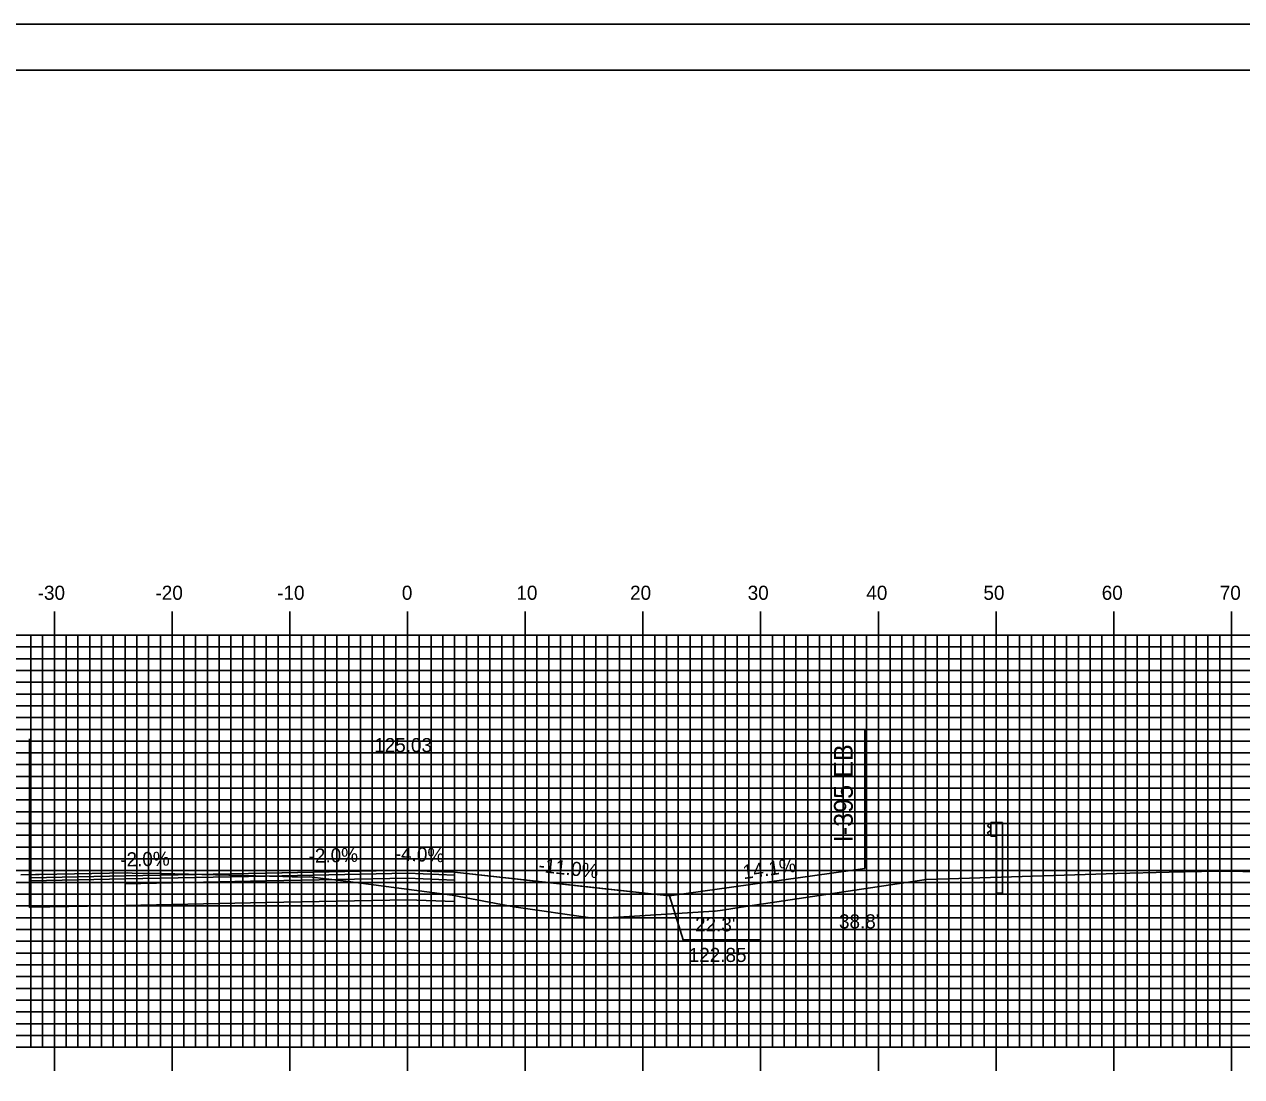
# Model space of a CAD drawing. Extents: x 853107 to 853450, y 366605 to 366825.
# Drawn here: x 853239.9 to 853343.4, y 366735.6 to 366824.9 of the extents above; entities that cross this region are included whole.
import ezdxf

# ---------------------------------------------------------------- set-up
doc = ezdxf.new("R2010")
doc.units = 0
for name, color, linetype in [('ANNOTATION', 7, 'Continuous'), ('BORDER', 7, 'Continuous'), ('D_Drainage_Underdrain', 7, 'Continuous'), ('D_Roadway_Centerline', 7, 'Continuous'), ('D_Roadway_Centerline_Text', 7, 'Continuous'), ('D_Roadway_Edge_Shoulder', 7, 'Continuous'), ('D_Roadway_Edge_TW', 7, 'Continuous'), ('D_Roadway_Pavement', 7, 'Continuous'), ('D_Roadway_SubGrade', 7, 'Continuous'), ('D_Text_Standard', 7, 'Continuous'), ('H_V ANNOTATION', 7, 'Continuous'), ('M_Guardrail', 7, 'Continuous'), ('M_Roadway_Centerline', 7, 'Continuous'), ('MAJOR', 7, 'Continuous'), ('MINOR', 7, 'Continuous'), ('PLOT BOUNDARY', 7, 'Continuous'), ('S_Roadway_Centerline', 7, 'Continuous')]:
    doc.layers.add(name, color=color, linetype=linetype)

msp = doc.modelspace()

# ---------------------------------------------------------------- linework, layer by layer
at = {"layer": 'ANNOTATION'}
msp.add_lwpolyline([(853302.45, 366747.17), (853295.91, 366747.17), (853294.76, 366750.91)], dxfattribs=at)
at = {"layer": 'BORDER'}
msp.add_lwpolyline([(853122.9, 366611.06), (853442.9, 366611.06), (853442.9, 366821.06), (853122.9, 366821.06)], close=True, dxfattribs=at)
at = {"layer": 'D_Drainage_Underdrain'}
msp.add_line((853240.42, 366752.43), (853240.39, 366752.44), dxfattribs=at)
at = {"layer": 'D_Roadway_Centerline'}
for p, q in [((853240.42, 366752.43), (853240.39, 366752.44)), ((853240.5, 366749.95), (853240.39, 366749.94))]:
    msp.add_line(p, q, dxfattribs=at)
for points in [[(853240.42, 366752.43), (853240.5, 366752.44), (853240.5, 366752.44), (853240.51, 366752.44), (853248.5, 366752.61), (853260.5, 366752.85), (853260.51, 366752.85), (853272.5, 366753.09), (853274.72, 366753), (853276.5, 366752.93), (853287.71, 366751.69), (853294.76, 366750.91)], [(853276.5, 366752.93), (853294.76, 366750.91)], [(853294.76, 366750.91), (853311.35, 366753.24)]]:
    msp.add_lwpolyline(points, dxfattribs=at)
at = {"layer": 'D_Roadway_Edge_Shoulder'}
for points in [[(853272.5, 366753.09), (853276.5, 366752.93), (853276.5, 366752.68), (853272.5, 366752.84)], [(853248.5, 366752.61), (853240.5, 366752.44), (853240.5, 366752.19), (853248.5, 366752.36)]]:
    msp.add_lwpolyline(points, close=True, dxfattribs=at)
at = {"layer": 'D_Roadway_Edge_TW'}
for points in [[(853260.5, 366752.85), (853248.5, 366752.61), (853248.5, 366752.36), (853260.5, 366752.6)], [(853272.5, 366753.09), (853260.5, 366752.85), (853260.5, 366752.6), (853272.5, 366752.84)]]:
    msp.add_lwpolyline(points, close=True, dxfattribs=at)
at = {"layer": 'D_Roadway_Pavement'}
for points in [[(853272.5, 366752.84), (853260.5, 366752.6), (853260.5, 366752.18), (853272.5, 366752.42)], [(853272.5, 366752.84), (853276.5, 366752.68), (853276.5, 366752.26), (853272.5, 366752.42)], [(853260.5, 366752.6), (853248.5, 366752.36), (853248.5, 366751.94), (853260.5, 366752.18)], [(853248.5, 366752.36), (853248.5, 366751.94), (853248.5, 366751.94)]]:
    msp.add_lwpolyline(points, close=True, dxfattribs=at)
msp.add_lwpolyline([(853260.5, 366752.6), (853260.5, 366752.18)], dxfattribs=at)
at = {"layer": 'D_Roadway_SubGrade'}
for p, q in [((853240.39, 366764.25), (853240.39, 366749.94)), ((853311.35, 366765.05), (853311.35, 366753.24)), ((853240.39, 366752.44), (853240.39, 366749.94))]:
    msp.add_line(p, q, dxfattribs=at)
for points in [[(853272.5, 366752.42), (853276.5, 366752.26), (853276.5, 366752.68), (853276.5, 366752.93), (853276.5, 366750.43), (853272.5, 366750.59)], [(853248.5, 366751.94), (853248.5, 366751.94), (853248.5, 366752.36), (853240.5, 366752.19), (853240.5, 366752.44), (853240.5, 366749.95), (853248.5, 366750.11)], [(853260.5, 366752.18), (853248.5, 366751.94), (853248.5, 366750.11), (853260.5, 366750.35)], [(853272.5, 366752.42), (853260.5, 366752.18), (853260.5, 366750.35), (853272.5, 366750.59)]]:
    msp.add_lwpolyline(points, close=True, dxfattribs=at)
at = {"layer": 'M_Guardrail'}
for p, q in [((853321.97, 366757.05), (853321.82, 366756.95)), ((853322.06, 366757.07), (853321.98, 366757.06)), ((853322.06, 366757.15), (853322.55, 366757.15)), ((853322.06, 366755.98), (853322.06, 366757.15)), ((853322.55, 366757.15), (853323.05, 366757.15)), ((853322.55, 366757.15), (853322.55, 366755.98)), ((853323.05, 366757.15), (853323.05, 366751.15)), ((853321.82, 366756.81), (853322.02, 366756.67)), ((853322.02, 366756.45), (853321.82, 366756.32)), ((853321.82, 366756.17), (853321.97, 366756.07)), ((853321.98, 366756.07), (853322.06, 366756.05)), ((853322.05, 366756.61), (853322.05, 366756.52)), ((853322.55, 366755.98), (853322.06, 366755.98)), ((853322.55, 366751.15), (853322.55, 366755.98)), ((853322.55, 366751.15), (853323.05, 366751.15))]:
    msp.add_line(p, q, dxfattribs=at)
for centre, major_axis, start_param, end_param in [((853321.87, 366756.88), (-0.0877, 0), 5.323254, 7.243116), ((853321.99, 366757.02), (-0.0417, 0), 4.886922, 5.323254), ((853321.87, 366756.25), (-0.0877, 0), 5.323254, 7.243116), ((853321.99, 366756.11), (-0.0417, 0), 0.959931, 1.396263), ((853321.97, 366756.61), (0.0789, 0), 0, 0.959931), ((853321.97, 366756.52), (0.0789, 0), 5.323254, 6.283185)]:
    msp.add_ellipse(centre, major_axis=major_axis, ratio=0.995501, start_param=start_param, end_param=end_param, dxfattribs=at)
at = {"layer": 'MAJOR'}
for p, q in [((853242.5, 366775.06), (853242.5, 366773.06)), ((853252.5, 366775.06), (853252.5, 366773.06)), ((853262.5, 366775.06), (853262.5, 366773.06)), ((853272.5, 366775.06), (853272.5, 366773.06)), ((853282.5, 366775.06), (853282.5, 366773.06)), ((853292.5, 366775.06), (853292.5, 366773.06)), ((853302.5, 366775.06), (853302.5, 366773.06)), ((853312.5, 366775.06), (853312.5, 366773.06)), ((853322.5, 366775.06), (853322.5, 366773.06)), ((853332.5, 366775.06), (853332.5, 366773.06)), ((853342.5, 366775.06), (853342.5, 366773.06)), ((853132.5, 366773.06), (853412.5, 366773.06)), ((853132.5, 366773.06), (853412.5, 366773.06)), ((853242.5, 366738.06), (853242.5, 366773.06)), ((853252.5, 366738.06), (853252.5, 366773.06)), ((853262.5, 366738.06), (853262.5, 366773.06)), ((853272.5, 366738.06), (853272.5, 366773.06)), ((853282.5, 366738.06), (853282.5, 366773.06)), ((853292.5, 366738.06), (853292.5, 366773.06)), ((853302.5, 366738.06), (853302.5, 366773.06)), ((853312.5, 366738.06), (853312.5, 366773.06)), ((853322.5, 366738.06), (853322.5, 366773.06)), ((853332.5, 366738.06), (853332.5, 366773.06)), ((853342.5, 366738.06), (853342.5, 366773.06)), ((853132.5, 366768.06), (853412.5, 366768.06)), ((853132.5, 366763.06), (853412.5, 366763.06)), ((853132.5, 366758.06), (853412.5, 366758.06)), ((853132.5, 366753.06), (853412.5, 366753.06)), ((853132.5, 366748.06), (853412.5, 366748.06)), ((853132.5, 366743.06), (853412.5, 366743.06)), ((853132.5, 366738.06), (853412.5, 366738.06)), ((853132.5, 366738.06), (853412.5, 366738.06)), ((853242.5, 366736.05), (853242.5, 366738.06)), ((853252.5, 366736.05), (853252.5, 366738.06)), ((853262.5, 366736.05), (853262.5, 366738.06)), ((853272.5, 366736.05), (853272.5, 366738.06)), ((853282.5, 366736.05), (853282.5, 366738.06)), ((853292.5, 366736.05), (853292.5, 366738.06)), ((853302.5, 366736.05), (853302.5, 366738.06)), ((853312.5, 366736.05), (853312.5, 366738.06)), ((853322.5, 366736.05), (853322.5, 366738.06)), ((853332.5, 366736.05), (853332.5, 366738.06)), ((853342.5, 366736.05), (853342.5, 366738.06))]:
    msp.add_line(p, q, dxfattribs=at)
at = {"layer": 'MINOR'}
for p, q in [((853240.5, 366738.06), (853240.5, 366773.06)), ((853241.5, 366738.06), (853241.5, 366773.06)), ((853243.5, 366738.06), (853243.5, 366773.06)), ((853244.5, 366738.06), (853244.5, 366773.06)), ((853245.5, 366738.06), (853245.5, 366773.06)), ((853246.5, 366738.06), (853246.5, 366773.06)), ((853247.5, 366738.06), (853247.5, 366773.06)), ((853248.5, 366738.06), (853248.5, 366773.06)), ((853249.5, 366738.06), (853249.5, 366773.06)), ((853250.5, 366738.06), (853250.5, 366773.06)), ((853251.5, 366738.06), (853251.5, 366773.06)), ((853253.5, 366738.06), (853253.5, 366773.06)), ((853254.5, 366738.06), (853254.5, 366773.06)), ((853255.5, 366738.06), (853255.5, 366773.06)), ((853256.5, 366738.06), (853256.5, 366773.06)), ((853257.5, 366738.06), (853257.5, 366773.06)), ((853258.5, 366738.06), (853258.5, 366773.06)), ((853259.5, 366738.06), (853259.5, 366773.06)), ((853260.5, 366738.06), (853260.5, 366773.06)), ((853261.5, 366738.06), (853261.5, 366773.06)), ((853263.5, 366738.06), (853263.5, 366773.06)), ((853264.5, 366738.06), (853264.5, 366773.06)), ((853265.5, 366738.06), (853265.5, 366773.06)), ((853266.5, 366738.06), (853266.5, 366773.06)), ((853267.5, 366738.06), (853267.5, 366773.06)), ((853268.5, 366738.06), (853268.5, 366773.06)), ((853269.5, 366738.06), (853269.5, 366773.06)), ((853270.5, 366738.06), (853270.5, 366773.06)), ((853271.5, 366738.06), (853271.5, 366773.06)), ((853273.5, 366738.06), (853273.5, 366773.06)), ((853274.5, 366738.06), (853274.5, 366773.06)), ((853275.5, 366738.06), (853275.5, 366773.06)), ((853276.5, 366738.06), (853276.5, 366773.06)), ((853277.5, 366738.06), (853277.5, 366773.06)), ((853278.5, 366738.06), (853278.5, 366773.06)), ((853279.5, 366738.06), (853279.5, 366773.06)), ((853280.5, 366738.06), (853280.5, 366773.06)), ((853281.5, 366738.06), (853281.5, 366773.06)), ((853283.5, 366738.06), (853283.5, 366773.06)), ((853284.5, 366738.06), (853284.5, 366773.06)), ((853285.5, 366738.06), (853285.5, 366773.06)), ((853286.5, 366738.06), (853286.5, 366773.06)), ((853287.5, 366738.06), (853287.5, 366773.06)), ((853288.5, 366738.06), (853288.5, 366773.06)), ((853289.5, 366738.06), (853289.5, 366773.06)), ((853290.5, 366738.06), (853290.5, 366773.06)), ((853291.5, 366738.06), (853291.5, 366773.06)), ((853293.5, 366738.06), (853293.5, 366773.06)), ((853294.5, 366738.06), (853294.5, 366773.06)), ((853295.5, 366738.06), (853295.5, 366773.06)), ((853296.5, 366738.06), (853296.5, 366773.06)), ((853297.5, 366738.06), (853297.5, 366773.06)), ((853298.5, 366738.06), (853298.5, 366773.06)), ((853299.5, 366738.06), (853299.5, 366773.06)), ((853300.5, 366738.06), (853300.5, 366773.06)), ((853301.5, 366738.06), (853301.5, 366773.06)), ((853303.5, 366738.06), (853303.5, 366773.06)), ((853304.5, 366738.06), (853304.5, 366773.06)), ((853305.5, 366738.06), (853305.5, 366773.06)), ((853306.5, 366738.06), (853306.5, 366773.06)), ((853307.5, 366738.06), (853307.5, 366773.06)), ((853308.5, 366738.06), (853308.5, 366773.06)), ((853309.5, 366738.06), (853309.5, 366773.06)), ((853310.5, 366738.06), (853310.5, 366773.06)), ((853311.5, 366738.06), (853311.5, 366773.06)), ((853313.5, 366738.06), (853313.5, 366773.06)), ((853314.5, 366738.06), (853314.5, 366773.06)), ((853315.5, 366738.06), (853315.5, 366773.06)), ((853316.5, 366738.06), (853316.5, 366773.06)), ((853317.5, 366738.06), (853317.5, 366773.06)), ((853318.5, 366738.06), (853318.5, 366773.06)), ((853319.5, 366738.06), (853319.5, 366773.06)), ((853320.5, 366738.06), (853320.5, 366773.06)), ((853321.5, 366738.06), (853321.5, 366773.06)), ((853323.5, 366738.06), (853323.5, 366773.06)), ((853324.5, 366738.06), (853324.5, 366773.06)), ((853325.5, 366738.06), (853325.5, 366773.06)), ((853326.5, 366738.06), (853326.5, 366773.06)), ((853327.5, 366738.06), (853327.5, 366773.06)), ((853328.5, 366738.06), (853328.5, 366773.06)), ((853329.5, 366738.06), (853329.5, 366773.06)), ((853330.5, 366738.06), (853330.5, 366773.06)), ((853331.5, 366738.06), (853331.5, 366773.06)), ((853333.5, 366738.06), (853333.5, 366773.06)), ((853334.5, 366738.06), (853334.5, 366773.06)), ((853335.5, 366738.06), (853335.5, 366773.06)), ((853336.5, 366738.06), (853336.5, 366773.06)), ((853337.5, 366738.06), (853337.5, 366773.06)), ((853338.5, 366738.06), (853338.5, 366773.06)), ((853339.5, 366738.06), (853339.5, 366773.06)), ((853340.5, 366738.06), (853340.5, 366773.06)), ((853341.5, 366738.06), (853341.5, 366773.06)), ((853132.5, 366772.06), (853412.5, 366772.06)), ((853132.5, 366771.06), (853412.5, 366771.06)), ((853132.5, 366770.06), (853412.5, 366770.06)), ((853132.5, 366769.06), (853412.5, 366769.06)), ((853132.5, 366767.06), (853412.5, 366767.06)), ((853132.5, 366766.06), (853412.5, 366766.06)), ((853132.5, 366765.06), (853412.5, 366765.06)), ((853132.5, 366764.06), (853412.5, 366764.06)), ((853132.5, 366762.06), (853412.5, 366762.06)), ((853132.5, 366761.06), (853412.5, 366761.06)), ((853132.5, 366760.06), (853412.5, 366760.06)), ((853132.5, 366759.06), (853412.5, 366759.06)), ((853132.5, 366757.06), (853412.5, 366757.06)), ((853132.5, 366756.06), (853412.5, 366756.06)), ((853132.5, 366755.06), (853412.5, 366755.06)), ((853132.5, 366754.06), (853412.5, 366754.06)), ((853132.5, 366752.06), (853412.5, 366752.06)), ((853132.5, 366751.06), (853412.5, 366751.06)), ((853132.5, 366750.06), (853412.5, 366750.06)), ((853132.5, 366749.06), (853412.5, 366749.06)), ((853132.5, 366747.06), (853412.5, 366747.06)), ((853132.5, 366746.06), (853412.5, 366746.06)), ((853132.5, 366745.06), (853412.5, 366745.06)), ((853132.5, 366744.06), (853412.5, 366744.06)), ((853132.5, 366742.06), (853412.5, 366742.06)), ((853132.5, 366741.06), (853412.5, 366741.06)), ((853132.5, 366740.06), (853412.5, 366740.06)), ((853132.5, 366739.06), (853412.5, 366739.06))]:
    msp.add_line(p, q, dxfattribs=at)
at = {"layer": 'PLOT BOUNDARY'}
msp.add_lwpolyline([(853106.72, 366604.94), (853446.72, 366604.94), (853446.72, 366824.94), (853106.72, 366824.94)], close=True, dxfattribs=at)
at = {"layer": 'S_Roadway_Centerline'}
msp.add_lwpolyline([(853239.65, 366752.7), (853240.89, 366752.73), (853241.21, 366752.74), (853248.67, 366752.88), (853249.11, 366752.85), (853251.6, 366752.82), (853261.9, 366752.56), (853263.46, 366752.51), (853264.13, 366752.52), (853267.04, 366752.2), (853276.29, 366750.98), (853281.54, 366749.99), (853288.24, 366749.02), (853289.98, 366749.09), (853298.55, 366749.62), (853298.64, 366749.62), (853299.27, 366749.71), (853300.85, 366749.95), (853316.57, 366752.31), (853317.56, 366752.33), (853332.75, 366752.82), (853337.2, 366752.94), (853341.31, 366753.02), (853341.42, 366753.01), (853345.51, 366752.96)], dxfattribs=at)

# ---------------------------------------------------------------- texts
at = {"layer": 'ANNOTATION'}
for s, height, rotation, p in [('I-395 EB', 1.6, 90, (853310.33, 366755.47)), ('-2.0%', 1.2, 1.1458, (853264.11, 366753.72)), ('-4.0%', 1.2, 357.7093, (853271.4, 366753.93)), ('-2.0%', 1.2, 1.1572, (853248.11, 366753.4)), ('-11.0%', 1.2, 353.6989, (853283.59, 366752.96)), ('14.1%', 1.2, 8.0017, (853301.06, 366752.33)), ("22.3' ", 1.2, 360, (853296.93, 366747.9)), ('122.85', 1.2, 360, (853296.39, 366745.3))]:
    msp.add_text(s, height=height, rotation=rotation, dxfattribs=at).set_placement(p)
at = {"layer": 'D_Roadway_Centerline_Text'}
msp.add_text('125.03', height=1.2, dxfattribs=at).set_placement((853269.67, 366763.12))
at = {"layer": 'D_Text_Standard'}
msp.add_text("38.8'", height=1.2, dxfattribs=at).set_placement((853309.16, 366748.15))
at = {"layer": 'H_V ANNOTATION'}
for s, p in [('-30', (853241.08, 366776.06)), ('-20', (853251.09, 366776.06)), ('-10', (853261.43, 366776.06)), ('0', (853272.02, 366776.06)), ('10', (853281.75, 366776.06)), ('20', (853291.41, 366776.06)), ('30', (853301.4, 366776.06)), ('40', (853311.48, 366776.06)), ('50', (853321.43, 366776.06)), ('60', (853331.48, 366776.06)), ('70', (853341.51, 366776.06))]:
    msp.add_text(s, height=1.2, dxfattribs=at).set_placement(p)
at = {"layer": 'M_Roadway_Centerline'}
for s, p in [('C', (853248.67, 366752.88)), ('L', (853248.67, 366752.87)), ('C', (853341.31, 366753.02)), ('L', (853341.31, 366753.01))]:
    msp.add_text(s, height=0.0146, dxfattribs=at).set_placement(p)

doc.saveas('drawing.dxf')
